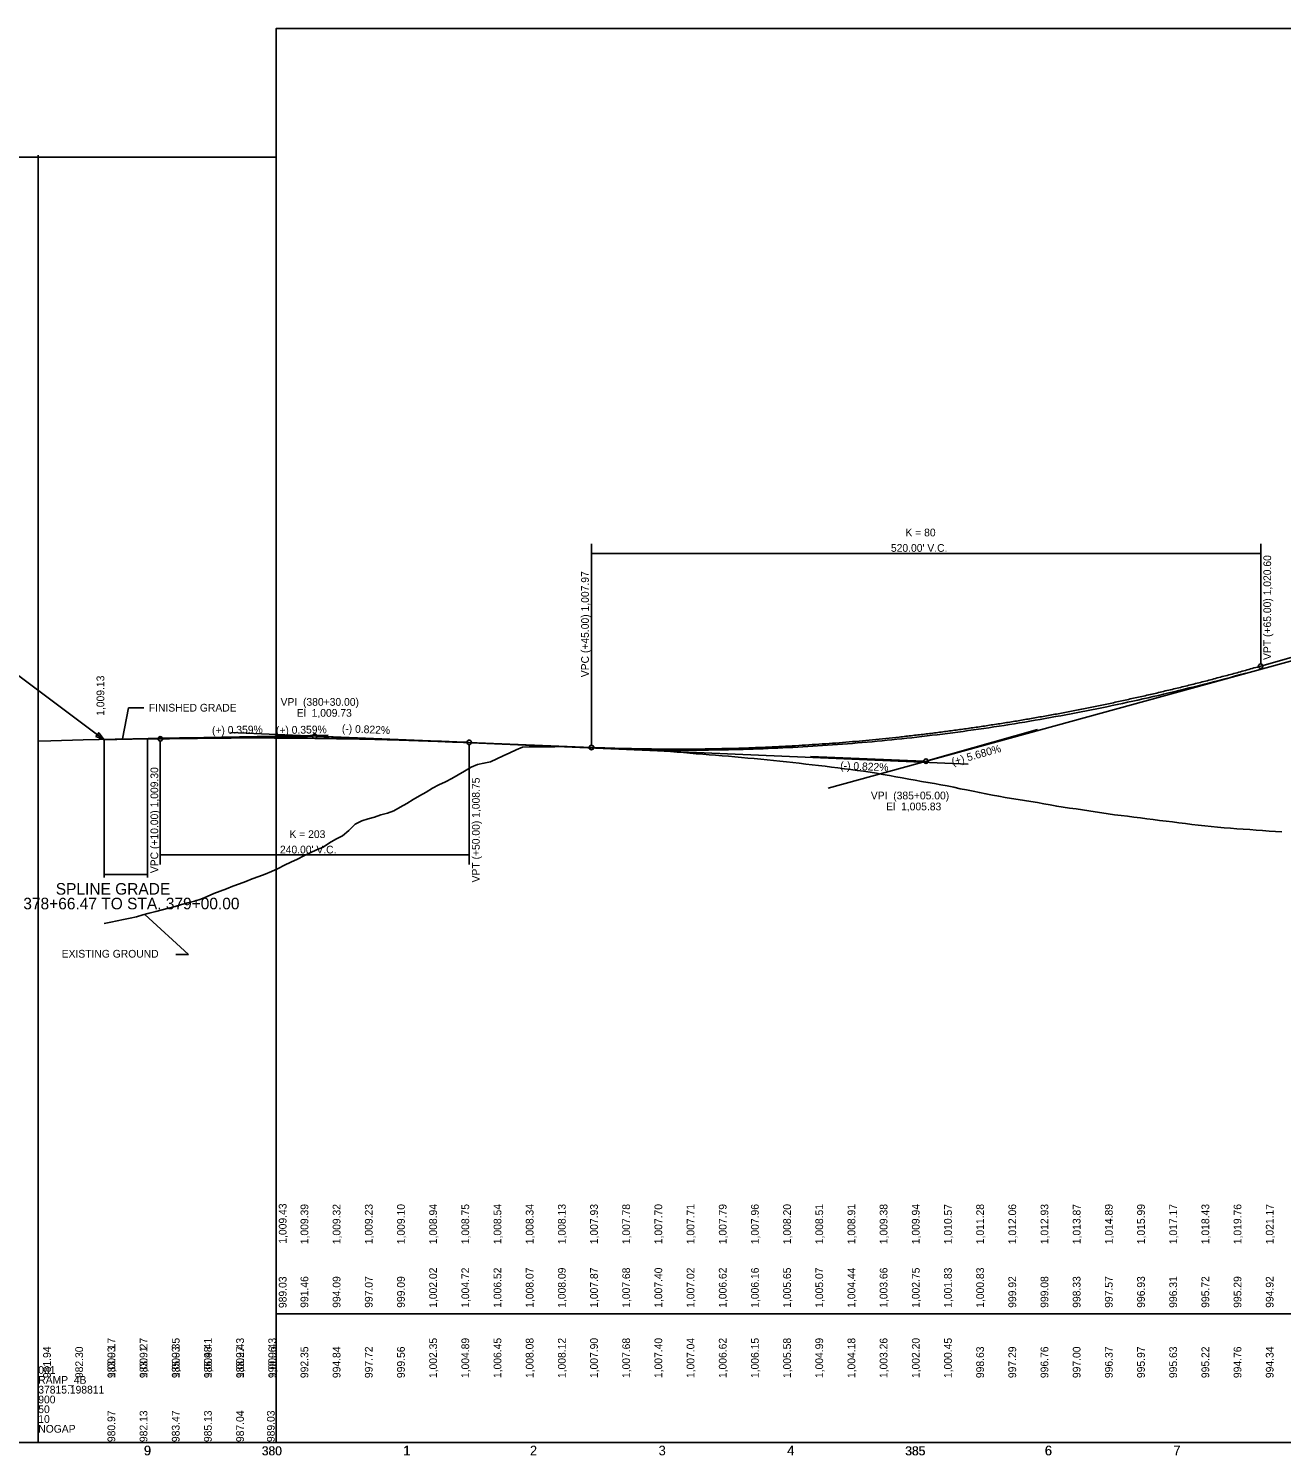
# Model space of a CAD drawing. Extents: x 150 to 16976893, y 3102 to 12559827.
# Drawn here: x 16972201 to 16973174, y 12558429 to 12559538 of the extents above; entities that cross this region are included whole.
import ezdxf

# ---------------------------------------------------------------- set-up
doc = ezdxf.new("R2010")
doc.units = 0
for name, color, linetype in [('Default', 7, 'Continuous'), ('Level 56', 7, 'Continuous'), ('RD_DDB_Ex_Tx', 7, 'Continuous'), ('RD_DDB_GradeTX', 7, 'Continuous'), ('RD_DDB_PI', 7, 'Continuous'), ('RD_DDB_Pr_Tx', 7, 'Continuous'), ('RD_DDB_Profile_EX', 7, 'Continuous'), ('RD_DDB_StaTX', 7, 'Continuous'), ('RD_DDB_StripGrade', 7, 'Continuous'), ('RD_DDB_StripGrade_EX', 7, 'Continuous'), ('RD_GPK_Profile_Cell', 7, 'Continuous'), ('RD_HC_TX_Sta20', 7, 'Continuous'), ('RD_TX_Profile', 7, 'Continuous'), ('RD_XS_Misc_Line', 7, 'Continuous')]:
    doc.layers.add(name, color=color, linetype=linetype)

msp = doc.modelspace()

# ---------------------------------------------------------------- linework, layer by layer
at = {"layer": 'Default'}
for p, q in [((16972821.8, 12558947.5), (16973560.3, 12559150.6)), ((16972357.4, 12558990.8), (16972930.5, 12558966.2)), ((16972208.1, 12558983.9), (16972217.9, 12558984.2)), ((16972217.9, 12558984.2), (16972242.9, 12558985)), ((16972242.9, 12558985), (16972267.9, 12558985.6)), ((16972267.9, 12558985.6), (16972433.4, 12558988.7))]:
    msp.add_line(p, q, dxfattribs=at)
for points in [[(16972392.9, 12558539.3), (16973892.9, 12558539.3), (16973892.9, 12559537.5), (16972392.9, 12559537.5)], [(16970892.9, 12558439.3), (16972392.9, 12558439.3), (16972392.9, 12559437.5), (16970892.9, 12559437.5)]]:
    msp.add_lwpolyline(points, close=True, dxfattribs=at)
for points in [[(16972644.1, 12558978.5), (16972895.2, 12558967.7), (16973146.3, 12559036.8)], [(16972293.6, 12558986.1), (16972413.6, 12558988.4), (16972533.6, 12558983.2)]]:
    msp.add_open_spline(points, degree=2, dxfattribs=at)
at = {"layer": 'RD_DDB_Ex_Tx'}
for p, q in [((16972324.9, 12558818.4), (16972290.8, 12558849.4)), ((16972315.1, 12558818.4), (16972324.9, 12558818.4))]:
    msp.add_line(p, q, dxfattribs=at)
at = {"layer": 'RD_DDB_PI'}
for p, q in [((16972984.5, 12558993.1), (16972899.6, 12558968.9)), ((16972332.9, 12558986.4), (16972421.1, 12558987.9)), ((16972512.8, 12558984.3), (16972424.6, 12558987.9)), ((16972808, 12558972.2), (16972896.2, 12558968.5))]:
    msp.add_line(p, q, dxfattribs=at)
for centre in [(16972422.9, 12558988), (16972897.9, 12558968.5)]:
    msp.add_circle(centre, 1.75, dxfattribs=at)
at = {"layer": 'RD_DDB_Pr_Tx'}
for q in [(16972273.6, 12558985.7), (16972290.2, 12559009.8)]:
    msp.add_line((16972278.3, 12559009.8), q, dxfattribs=at)
at = {"layer": 'RD_DDB_Profile_EX'}
for points in [[(16972259.4, 12558842.4), (16972264.4, 12558843.4), (16972269.4, 12558844.4), (16972274.4, 12558845.5), (16972279.4, 12558846.6), (16972284.4, 12558847.7), (16972289.4, 12558849), (16972294.4, 12558850.4), (16972299.4, 12558851.7), (16972304.4, 12558853), (16972309.4, 12558854.4), (16972314.4, 12558855.7), (16972319.4, 12558857.1), (16972324.4, 12558858.4), (16972329.4, 12558859.7), (16972334.4, 12558861.3), (16972339.4, 12558863.3), (16972344.4, 12558865.6), (16972349.4, 12558867.5), (16972354.4, 12558869.4), (16972359.4, 12558871.3), (16972364.4, 12558873.2), (16972369.4, 12558875.1), (16972374.4, 12558877), (16972379.4, 12558878.9), (16972384.4, 12558880.8), (16972389.4, 12558882.7), (16972394.4, 12558885.2), (16972399.4, 12558887.6), (16972404.4, 12558890), (16972409.4, 12558892.4), (16972414.4, 12558894.9), (16972419.4, 12558897.3), (16972424.4, 12558899.5), (16972429.4, 12558901.8), (16972434.4, 12558905), (16972439.4, 12558907.9), (16972444.4, 12558910.5), (16972449.4, 12558914.5), (16972454.4, 12558919.5), (16972459.4, 12558922.1), (16972464.4, 12558923.6), (16972469.4, 12558925.1), (16972474.4, 12558926.7), (16972479.4, 12558928.2), (16972484.4, 12558929.8), (16972489.4, 12558932.7), (16972494.4, 12558935.6), (16972499.4, 12558938.6), (16972504.4, 12558941.5), (16972509.4, 12558944.5), (16972514.4, 12558947.4), (16972519.4, 12558950.2), (16972524.4, 12558952.5), (16972529.4, 12558954.9), (16972534.4, 12558957.8), (16972539.4, 12558960.8), (16972544.4, 12558963.8), (16972549.4, 12558966), (16972554.4, 12558966.8), (16972559.4, 12558968), (16972564.4, 12558970.3), (16972569.4, 12558972.6), (16972574.4, 12558974.9), (16972579.4, 12558977.2), (16972584.4, 12558979.4), (16972589.4, 12558979.7), (16972594.4, 12558979.7), (16972599.4, 12558979.7), (16972604.4, 12558979.7), (16972609.4, 12558979.7), (16972614.4, 12558979.8), (16972619.4, 12558979.7), (16972624.4, 12558979.6), (16972629.4, 12558979.4), (16972634.4, 12558979.2), (16972639.4, 12558978.9), (16972644.4, 12558978.6), (16972649.4, 12558978.4), (16972654.4, 12558978.3), (16972659.4, 12558978.1), (16972664.4, 12558977.9), (16972669.4, 12558977.6), (16972674.4, 12558977.4), (16972679.4, 12558977.1), (16972684.4, 12558976.9), (16972689.4, 12558976.5), (16972694.4, 12558976.2), (16972699.4, 12558975.9), (16972704.4, 12558975.5), (16972709.4, 12558975.2), (16972714.4, 12558974.7), (16972719.4, 12558974.3), (16972724.4, 12558973.9), (16972729.4, 12558973.5), (16972734.4, 12558973.1), (16972739.4, 12558972.7), (16972744.4, 12558972.3), (16972749.4, 12558971.9), (16972754.4, 12558971.4), (16972759.4, 12558970.9)], [(16972759.4, 12558970.9), (16972764.4, 12558970.5), (16972769.4, 12558970), (16972774.4, 12558969.5), (16972779.4, 12558968.9), (16972784.4, 12558968.4), (16972789.4, 12558967.9), (16972794.4, 12558967.4), (16972799.4, 12558966.8), (16972804.4, 12558966.2), (16972809.4, 12558965.6), (16972814.4, 12558965), (16972819.4, 12558964.5), (16972824.4, 12558963.9), (16972829.4, 12558963.3), (16972834.4, 12558962.6), (16972839.4, 12558962), (16972844.4, 12558961.3), (16972849.4, 12558960.6), (16972854.4, 12558959.9), (16972859.4, 12558959.1), (16972864.4, 12558958.2), (16972869.4, 12558957.3), (16972874.4, 12558956.4), (16972879.4, 12558955.5), (16972884.4, 12558954.6), (16972889.4, 12558953.7), (16972894.4, 12558952.8), (16972899.4, 12558952), (16972904.4, 12558951.1), (16972909.4, 12558950.1), (16972914.4, 12558949.2), (16972919.4, 12558948.2), (16972924.4, 12558947.1), (16972929.4, 12558946.2), (16972934.4, 12558945.2), (16972939.4, 12558944.1), (16972944.4, 12558943.2), (16972949.4, 12558942.2), (16972954.4, 12558941.2), (16972959.4, 12558940.3), (16972964.4, 12558939.5), (16972969.4, 12558938.7), (16972974.4, 12558937.9), (16972979.4, 12558937.1), (16972984.4, 12558936.3), (16972989.4, 12558935.4), (16972994.4, 12558934.5), (16972999.4, 12558933.5), (16973004.4, 12558932.8), (16973009.4, 12558932.1), (16973014.4, 12558931.4), (16973019.4, 12558930.8), (16973024.4, 12558929.9), (16973029.4, 12558929), (16973034.4, 12558928.3), (16973039.4, 12558927.6), (16973044.4, 12558926.9), (16973049.4, 12558926.3), (16973054.4, 12558925.7), (16973059.4, 12558925.1), (16973064.4, 12558924.4), (16973069.4, 12558923.8), (16973074.4, 12558923.2), (16973079.4, 12558922.5), (16973084.4, 12558921.9), (16973089.4, 12558921.3), (16973094.4, 12558920.7), (16973099.4, 12558920), (16973104.4, 12558919.4), (16973109.4, 12558918.8), (16973114.4, 12558918.3), (16973119.4, 12558917.8), (16973124.4, 12558917.3), (16973129.4, 12558916.8), (16973134.4, 12558916.4), (16973139.4, 12558916), (16973144.4, 12558915.7), (16973149.4, 12558915.3), (16973154.4, 12558915), (16973159.4, 12558914.6), (16973164.4, 12558914.2), (16973169.4, 12558913.8), (16973174.4, 12558913.5)]]:
    msp.add_lwpolyline(points, dxfattribs=at)
at = {"layer": 'RD_DDB_StripGrade'}
for p, q in [((16972259.4, 12558878), (16972259.4, 12558985)), ((16972292.9, 12558878), (16972292.9, 12558985.7)), ((16972259.4, 12558880.4), (16972292.9, 12558880.4))]:
    msp.add_line(p, q, dxfattribs=at)
at = {"layer": 'RD_GPK_Profile_Cell'}
for q in [(16972208.1, 12559439.3), (16976677.1, 12558439.3), (16972208.1, 12558439.3)]:
    msp.add_line((16972208.1, 12558439.3), q, dxfattribs=at)
at = {"layer": 'RD_HC_TX_Sta20'}
for p, q in [((16972637.9, 12559137.3), (16972637.9, 12558980.9)), ((16972637.9, 12559137.3), (16972637.9, 12558980.9)), ((16973157.9, 12559137.3), (16973157.9, 12559044.1)), ((16972637.9, 12559129.8), (16973157.9, 12559129.8)), ((16972637.9, 12559129.8), (16972642.9, 12559129.8)), ((16972302.9, 12558888.1), (16972302.9, 12558984.1)), ((16972542.9, 12558888.1), (16972542.9, 12558981.3)), ((16972302.9, 12558895.6), (16972542.9, 12558895.6))]:
    msp.add_line(p, q, dxfattribs=at)
for centre in [(16973157.9, 12559042.3), (16972302.9, 12558985.8), (16972542.9, 12558983.1), (16972637.9, 12558979.1), (16972637.9, 12558979.1)]:
    msp.add_circle(centre, 1.75, dxfattribs=at)
at = {"layer": 'RD_TX_Profile'}
msp.add_lwpolyline([(16972185.8, 12559035.6), (16972192.1, 12559035.6), (16972259.4, 12558985)], dxfattribs=at)
msp.add_lwpolyline([(16972252.9, 12558987.6), (16972259.4, 12558985), (16972255.1, 12558990.5)], close=True, dxfattribs=at)
at = {"layer": 'RD_XS_Misc_Line'}
for p, q in [((16973157.9, 12559042.3), (16973187.9, 12559050.8)), ((16972259.4, 12558985), (16972269.2, 12558985.2)), ((16972269.2, 12558985.2), (16972292.9, 12558985.7)), ((16972292.9, 12558985.7), (16972302.9, 12558985.8)), ((16972542.9, 12558983.1), (16972637.9, 12558979.1))]:
    msp.add_line(p, q, dxfattribs=at)
for points in [[(16972637.9, 12558979.1), (16972648.3, 12558978.8), (16972658.7, 12558978.4), (16972669.1, 12558978.2), (16972679.5, 12558978), (16972689.9, 12558977.9), (16972700.3, 12558977.8), (16972710.7, 12558977.8), (16972721.1, 12558977.9), (16972731.5, 12558978), (16972741.9, 12558978.3), (16972752.3, 12558978.5), (16972762.7, 12558978.9), (16972773.1, 12558979.3), (16972783.5, 12558979.8), (16972793.9, 12558980.3), (16972804.3, 12558981), (16972814.7, 12558981.7), (16972825.1, 12558982.4), (16972835.5, 12558983.2), (16972845.9, 12558984.1), (16972856.3, 12558985.1), (16972866.7, 12558986.1), (16972877.1, 12558987.2), (16972887.5, 12558988.4), (16972897.9, 12558989.6), (16972908.3, 12558990.9), (16972918.7, 12558992.3), (16972929.1, 12558993.7), (16972939.5, 12558995.2), (16972949.9, 12558996.8), (16972960.3, 12558998.4), (16972970.7, 12559000.1), (16972981.1, 12559001.9), (16972991.5, 12559003.7), (16973001.9, 12559005.6), (16973012.3, 12559007.6), (16973022.7, 12559009.6), (16973033.1, 12559011.7), (16973043.5, 12559013.9), (16973053.9, 12559016.2), (16973064.3, 12559018.5), (16973074.7, 12559020.8), (16973085.1, 12559023.3), (16973095.5, 12559025.8), (16973105.9, 12559028.4), (16973116.3, 12559031), (16973126.7, 12559033.8), (16973137.1, 12559036.5), (16973147.5, 12559039.4), (16973157.9, 12559042.3)], [(16972302.9, 12558985.8), (16972307.7, 12558985.9), (16972312.5, 12558986), (16972317.3, 12558986.1), (16972322.1, 12558986.1), (16972326.9, 12558986.2), (16972331.7, 12558986.2), (16972336.5, 12558986.3), (16972341.3, 12558986.3), (16972346.1, 12558986.4), (16972350.9, 12558986.4), (16972355.7, 12558986.4), (16972360.5, 12558986.5), (16972365.3, 12558986.5), (16972370.1, 12558986.5), (16972374.9, 12558986.5), (16972379.7, 12558986.5), (16972384.5, 12558986.5), (16972389.3, 12558986.5), (16972394.1, 12558986.4), (16972398.9, 12558986.4), (16972403.7, 12558986.4), (16972408.5, 12558986.4), (16972413.3, 12558986.3), (16972418.1, 12558986.3), (16972422.9, 12558986.2), (16972427.7, 12558986.2), (16972432.5, 12558986.1), (16972437.3, 12558986), (16972442.1, 12558985.9), (16972446.9, 12558985.9), (16972451.7, 12558985.8), (16972456.5, 12558985.7), (16972461.3, 12558985.6), (16972466.1, 12558985.5), (16972470.9, 12558985.4), (16972475.7, 12558985.3), (16972480.5, 12558985.1), (16972485.3, 12558985), (16972490.1, 12558984.9), (16972494.9, 12558984.7), (16972499.7, 12558984.6), (16972504.5, 12558984.4), (16972509.3, 12558984.3), (16972514.1, 12558984.1), (16972518.9, 12558984), (16972523.7, 12558983.8), (16972528.5, 12558983.6), (16972533.3, 12558983.4), (16972538.1, 12558983.2), (16972542.9, 12558983.1)]]:
    msp.add_spline(points, degree=3, dxfattribs=at)

# ---------------------------------------------------------------- texts
at = {"layer": 'Level 56'}
for s, p in [('1,009.43', (16972401, 12558593.7)), ('1,009.39', (16972417.9, 12558593.3)), ('1,009.32', (16972442.9, 12558593.3)), ('1,009.23', (16972467.9, 12558593.3)), ('1,009.10', (16972492.9, 12558593.3)), ('1,008.94', (16972517.9, 12558593.3)), ('1,008.75', (16972542.9, 12558593.3)), ('1,008.54', (16972567.9, 12558593.3)), ('1,008.34', (16972592.9, 12558593.3)), ('1,008.13', (16972617.9, 12558593.3)), ('1,007.93', (16972642.9, 12558593.3)), ('1,007.78', (16972667.9, 12558593.3)), ('1,007.70', (16972692.9, 12558593.3)), ('1,007.71', (16972717.9, 12558593.3)), ('1,007.79', (16972742.9, 12558593.3)), ('1,007.96', (16972767.9, 12558593.3)), ('1,008.20', (16972792.9, 12558593.3)), ('1,008.51', (16972817.9, 12558593.3)), ('1,008.91', (16972842.9, 12558593.3)), ('1,009.38', (16972867.9, 12558593.3)), ('1,009.94', (16972892.9, 12558593.3)), ('1,010.57', (16972917.9, 12558593.3)), ('1,011.28', (16972942.9, 12558593.3)), ('1,012.06', (16972967.9, 12558593.3)), ('1,012.93', (16972992.9, 12558593.3)), ('1,013.87', (16973017.9, 12558593.3)), ('1,014.89', (16973042.9, 12558593.3)), ('1,015.99', (16973067.9, 12558593.3)), ('1,017.17', (16973092.9, 12558593.3)), ('1,018.43', (16973117.9, 12558593.3)), ('1,019.76', (16973142.9, 12558593.3)), ('1,021.17', (16973167.9, 12558593.3)), ('981.94', (16972217.9, 12558489.3)), ('1,009.17', (16972267.9, 12558489.3)), ('1,009.27', (16972292.9, 12558489.3)), ('1,009.35', (16972317.9, 12558489.3)), ('1,009.41', (16972342.9, 12558489.3)), ('1,009.43', (16972367.9, 12558489.3)), ('1,009.43', (16972392.9, 12558489.3)), ('994.84', (16972442.9, 12558489.3)), ('1,002.35', (16972517.9, 12558489.3)), ('1,004.89', (16972542.9, 12558489.3)), ('1,006.45', (16972567.9, 12558489.3)), ('1,008.08', (16972592.9, 12558489.3)), ('1,008.12', (16972617.9, 12558489.3)), ('1,007.90', (16972642.9, 12558489.3)), ('1,007.68', (16972667.9, 12558489.3)), ('1,007.40', (16972692.9, 12558489.3)), ('1,007.04', (16972717.9, 12558489.3)), ('1,006.62', (16972742.9, 12558489.3)), ('1,006.15', (16972767.9, 12558489.3)), ('1,005.58', (16972792.9, 12558489.3)), ('1,004.99', (16972817.9, 12558489.3)), ('1,004.18', (16972842.9, 12558489.3)), ('1,003.26', (16972867.9, 12558489.3)), ('1,002.20', (16972892.9, 12558489.3)), ('1,000.45', (16972917.9, 12558489.3)), ('994.34', (16973167.9, 12558489.3)), ('982.30', (16972242.9, 12558489.3)), ('983.03', (16972267.9, 12558489.3)), ('983.91', (16972292.9, 12558489.3)), ('985.03', (16972317.9, 12558489.3)), ('986.48', (16972342.9, 12558489.3)), ('988.27', (16972367.9, 12558489.3)), ('990.06', (16972392.9, 12558489.3)), ('992.35', (16972417.9, 12558489.3)), ('997.72', (16972467.9, 12558489.3)), ('999.56', (16972492.9, 12558489.3)), ('998.63', (16972942.9, 12558489.3)), ('997.29', (16972967.9, 12558489.3)), ('996.76', (16972992.9, 12558489.3)), ('997.00', (16973017.9, 12558489.3)), ('996.37', (16973042.9, 12558489.3)), ('995.97', (16973067.9, 12558489.3)), ('995.63', (16973092.9, 12558489.3)), ('995.22', (16973117.9, 12558489.3)), ('994.76', (16973142.9, 12558489.3))]:
    msp.add_text(s, height=6, rotation=90, dxfattribs=at).set_placement(p)
at = {"layer": 'RD_DDB_Ex_Tx'}
msp.add_text('EXISTING GROUND', height=6, dxfattribs=at).set_placement((16972226.3, 12558815.9))
at = {"layer": 'RD_DDB_GradeTX'}
for s, rotation, p in [('(+) 0.359%', 1.0271, (16972343.1, 12558989.5)), ('(+) 0.359%', 1.0271, (16972392.8, 12558989.5)), ('(-) 0.822%', 357.6474, (16972443.9, 12558991)), ('(+) 5.680%', 15.8556, (16972918.7, 12558965)), ('(-) 0.822%', 357.6474, (16972831.1, 12558962.2))]:
    msp.add_text(s, height=6, rotation=rotation, dxfattribs=at).set_placement(p)
at = {"layer": 'RD_DDB_PI'}
msp.add_text('1,009.13', height=6, rotation=90, dxfattribs=at).set_placement((16972259.4, 12559003.7))
for s, p in [('VPI  (380+30.00)', (16972396.4, 12559011.5)), ('El  1,009.73', (16972408.9, 12559003)), ('VPI  (385+05.00)', (16972855, 12558938.8)), ('El  1,005.83', (16972866.9, 12558930.3))]:
    msp.add_text(s, height=6, dxfattribs=at).set_placement(p)
at = {"layer": 'RD_DDB_Pr_Tx'}
msp.add_text('FINISHED GRADE', height=6, dxfattribs=at).set_placement((16972294, 12559007))
at = {"layer": 'RD_DDB_StaTX'}
for s, height, p in [('9', 7.5, (16972290.1, 12558429.3)), ('9', 7.5, (16972290.3, 12558429.3)), ('9', 7.5, (16972290.3, 12558429.3)), ('9', 7.5, (16972290.3, 12558429.3)), ('380', 7, (16972381.7, 12558429.3)), ('380', 7, (16972381.7, 12558429.3)), ('380', 7, (16972381.7, 12558429.3)), ('380', 7, (16972381.9, 12558429.3)), ('1', 7.5, (16972491.6, 12558429.3)), ('1', 7.5, (16972491.9, 12558429.3)), ('1', 7.5, (16972491.9, 12558429.3)), ('1', 7.5, (16972491.9, 12558429.3)), ('2', 7.5, (16972590.1, 12558429.3)), ('2', 7.5, (16972590.1, 12558429.3)), ('2', 7.5, (16972590.1, 12558429.3)), ('2', 7.5, (16972590.1, 12558429.3)), ('3', 7.5, (16972690.1, 12558429.3)), ('3', 7.5, (16972690.1, 12558429.3)), ('4', 7.5, (16972789.9, 12558429.3)), ('4', 7.5, (16972790.1, 12558429.3)), ('385', 7, (16972881.6, 12558429.3)), ('385', 7, (16972881.9, 12558429.3)), ('6', 7.5, (16972990.1, 12558429.3)), ('6', 7.5, (16972990.3, 12558429.3)), ('7', 7.5, (16973090, 12558429.3)), ('7', 7.5, (16973090.1, 12558429.3))]:
    msp.add_text(s, height=height, dxfattribs=at).set_placement(p)
at = {"layer": 'RD_DDB_StripGrade'}
for s, p in [('SPLINE GRADE', (16972221.7, 12558864.8)), ('STA. 378+66.47 TO STA. 379+00.00', (16972166.4, 12558853.4))]:
    msp.add_text(s, height=9, dxfattribs=at).set_placement(p)
at = {"layer": 'RD_DDB_StripGrade_EX'}
for s, p in [('1,002.02', (16972517.9, 12558543.9)), ('1,004.72', (16972542.9, 12558543.9)), ('1,006.52', (16972567.9, 12558543.9)), ('1,008.07', (16972592.9, 12558543.9)), ('1,008.09', (16972617.9, 12558543.9)), ('1,007.87', (16972642.9, 12558543.9)), ('1,007.68', (16972667.9, 12558543.9)), ('1,007.40', (16972692.9, 12558543.9)), ('1,007.02', (16972717.9, 12558543.9)), ('1,006.62', (16972742.9, 12558543.9)), ('1,006.16', (16972767.9, 12558543.9)), ('1,005.65', (16972792.9, 12558543.9)), ('1,005.07', (16972817.9, 12558543.9)), ('1,004.44', (16972842.9, 12558543.9)), ('1,003.66', (16972867.9, 12558543.9)), ('1,002.75', (16972892.9, 12558543.9)), ('1,001.83', (16972917.9, 12558543.9)), ('1,000.83', (16972942.9, 12558543.9)), ('989.03', (16972401, 12558543.7)), ('991.46', (16972417.9, 12558543.9)), ('994.09', (16972442.9, 12558543.9)), ('997.07', (16972467.9, 12558543.9)), ('999.09', (16972492.9, 12558543.9)), ('999.92', (16972967.9, 12558543.9)), ('999.08', (16972992.9, 12558543.9)), ('998.33', (16973017.9, 12558543.9)), ('997.57', (16973042.9, 12558543.9)), ('996.93', (16973067.9, 12558543.9)), ('996.31', (16973092.9, 12558543.9)), ('995.72', (16973117.9, 12558543.9)), ('995.29', (16973142.9, 12558543.9)), ('994.92', (16973167.9, 12558543.9)), ('980.97', (16972267.9, 12558439.6)), ('982.13', (16972292.9, 12558439.6)), ('983.47', (16972317.9, 12558439.6)), ('985.13', (16972342.9, 12558439.6)), ('987.04', (16972367.9, 12558439.6)), ('989.03', (16972391.8, 12558439.6))]:
    msp.add_text(s, height=6, rotation=90, dxfattribs=at).set_placement(p)
at = {"layer": 'RD_GPK_Profile_Cell'}
for s, p in [('001', (16972208.1, 12558492.6)), ('37815.198811', (16972208.1, 12558477.3)), ('RAMP_4B', (16972208.1, 12558484.9)), ('900', (16972208.1, 12558469.7)), ('50', (16972208.1, 12558462.1)), ('10', (16972208.1, 12558454.5)), ('NOGAP', (16972208.1, 12558446.9))]:
    msp.add_text(s, height=6, dxfattribs=at).set_placement(p)
at = {"layer": 'RD_HC_TX_Sta20'}
for s, p in [('K = 80', (16972881.9, 12559143.1)), ("520.00' V.C.", (16972870.6, 12559131.1)), ('K = 203', (16972403.3, 12558908.8)), ("240.00' V.C.", (16972395.9, 12558896.8))]:
    msp.add_text(s, height=6, dxfattribs=at).set_placement(p)
for s, p in [('VPT (+65.00) 1,020.60', (16973166, 12559047.1)), ('VPC (+45.00) 1,007.97', (16972635.9, 12559033.7)), ('VPC (+45.00) 1,007.97', (16972635.9, 12559033.7)), ('VPC (+10.00) 1,009.30', (16972301.3, 12558881.5)), ('VPT (+50.00) 1,008.75', (16972551.1, 12558874.3))]:
    msp.add_text(s, height=6, rotation=90, dxfattribs=at).set_placement(p)

doc.saveas('drawing.dxf')
